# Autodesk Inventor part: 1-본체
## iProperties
Created: 2014-11
Part Number: 1-본체
Document SubType Name: Modeling
Designer: elite
Density: 2.71 g/cm^3
Material: 알루미늄-6061
Mass: 2880.96 g
Surface Area: 2086.61 cm^2
Volume: 1063.08 cm^3
Author: elite
